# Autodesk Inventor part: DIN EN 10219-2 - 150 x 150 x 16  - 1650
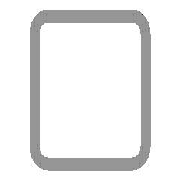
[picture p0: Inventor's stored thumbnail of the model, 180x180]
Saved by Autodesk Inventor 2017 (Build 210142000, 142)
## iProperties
Created: 2016-02
Part Number: DIN EN 10219-2 - 150 x 150 x 16  - 1650
Material: Steel, Mild
Description: Cold formed welded structural hollow sections of non-alloy and fine grain structural steel
Document SubType Name: Modeling
Standard: DIN
Designer: iusti
Standard Revision: 2006-07
Standards Organization: DIN
Language: en-US
Size Designation: 150 x 150 x 16
Categories: <MemberInstance><Categories><Category DisplayName="Structural Shapes" InternalName="089c4875-fa83-4c05-b084-43b9cc11f5ed" Mnemonic="GRDR"><CategoryParameter Dis
Stock Number: 150 x 150 x 16
Density: 7.85 g/cm^3
Appearance: Semi-Polished
Mass: 88044.5 g
Surface Area: 14231.3 cm^2
Volume: 11215.9 cm^3
G_L: 1650.000 mm
G_W: 150.000 mm
G_H: 150.000 mm
+B125B8ED-1570-405A-A825-64B3EFBC6DC3+CUTDETAIL1: Miter 45.00 deg
+1BFDA885-F50F-46B1-BDA8-57B8AE23BE4C+CUTDETAIL2: Miter 45.00 deg
_CCFamilyMember: 76
_CCFamilyDisplayName: DIN EN 10219-2 (Square Hollow Section - Cold Formed) - Cold formed welded structural hollow sections of non-alloy and fine grain structural steel
_FrameMemberDoc: Frame Member File
_Version: 15.0.0
_GetPNFromCC: 1
Author: iusti
IsCustomPart: 1
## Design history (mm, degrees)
node "Start plane"
node "End plane"
sketch "Sketch"
  geometry: L1 (-75, -27)-(-75, 27); L2 (-27, 75)-(27, 75); L3 (75, 27)-(75, -27); L4 (27, -75)-(-27, -75); L5 (-27, 59)-(27, 59); L6 (59, 27)-(59, -27); L7 (27, -59)-(-27, -59); L8 (-59, -27)-(-59, 27); L9 (0, 118.918)-(0, -118.918) reference; L10 (-118.918, 0)-(118.918, 0) reference; A1 r 48 centre (-27, -27) between (-75, -27) and (-27, -75); A2 r 48 centre (-27, 27) between (-27, 75) and (-75, 27); A3 r 48 centre (27, 27) between (75, 27) and (27, 75); A4 r 48 centre (27, -27) between (27, -75) and (75, -27); A5 r 32 centre (-27, 27) between (-27, 59) and (-59, 27); A6 r 32 centre (27, 27) between (59, 27) and (27, 59); A7 r 32 centre (27, -27) between (27, -59) and (59, -27); A8 r 32 centre (-27, -27) between (-59, -27) and (-27, -59)
  constraints: 16 end point, 16 point on circle, 8 centre point, 8 tangent, 4 parallel, 3 equal radius, 2 perpendicular, 7 other
  dimensions: "d7" = 48 radius of A1 (= G_IR); "d10" = 150 distance between parallel lines of L2 L4 (= G_H); "d11" = 150 distance between parallel lines of L1 L3 (= G_W); "d12" = 16 distance between parallel lines of L3 L6 (= G_T); "d15" = 75 distance between parallel lines of L2 L10 (= 0.5 x d10); "d16" = 75 distance between parallel lines of L9 L3 (= 0.5 x d11)
extrude "Body" new body sketch "Sketch" stored distance "d3" = 1650 (= G_L); taper "d4" = 0 deg
node "Driven Length"
  sketch "Sketch3"
    geometry: L1 (0, 0)-(10, 0) reference
    constraints: 2 end point, 1 horizontal
  workplane "Work Plane3"
  sketch "Sketch4"
    geometry: L1 (-2, -75)-(12, -75) reference; L2 (-2, 1575)-(12, 1575) reference
    dimensions: "d18" = 1650 distance between parallel lines of L1 L2 (derived)
workplane "Work Plane4"
split "Split1"
workplane "Work Plane5"
split "Split2"
body "Solid1"
other parameters: "G_W" = 150 [user parameter; used in 1 equation term], "G_H" = 150 [user parameter; used in 1 equation term], "G_T" = 16 [user parameter; used in 1 equation term], "G_IR" = 48 [user parameter; used in 1 equation term], "G_L" = 1650 (= d18) [user parameter; used in 1 equation term], "G_OFFSET_START" = 75 [user parameter; used in 1 equation term], "G_OFFSET_END" = 75 [user parameter; used in 1 equation term], "d13" = -75 (= -G_OFFSET_START), "d14" = 1575 (= G_OFFSET_END + B_L), "d17" = 90 deg
